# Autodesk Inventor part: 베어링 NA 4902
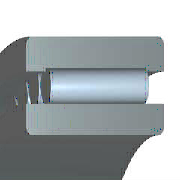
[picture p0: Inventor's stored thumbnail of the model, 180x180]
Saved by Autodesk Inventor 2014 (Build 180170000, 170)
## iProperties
IsCustomPart: 0
Manager: KYOUNG IL JANG
Company: 한국ATC센터
Created: 2009-02
Part Number: 베어링 NA 4902
Material: Steel, Mild
Description: 니들 롤러 베어링 - 경계 치수 및 공차
Document SubType Name: Modeling
Standard: KS B 2029
Standards Organization: KS
Language: ko-KR
Size Designation: NA 4902 - 15 x 28 x 13
Categories: <MemberInstance><Categories><Category DisplayName="샤프트 부품" InternalName="7f7aeb1f-a693-4053-b835-cee3144e0d98" Mnemonic="SHFT"><Category DisplayName="베어링" Inter
Density: 1 g/cm^3
Checked By: KYOUNG IL JANG
Vendor: CBT Solutions
Designer: KYOUNG IL JANG
Appearance: _시험-파란색 크롬
Author: KYOUNG IL JANG
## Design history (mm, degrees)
revolve "본체" stored, may be unused: angle "d17" = 90 deg
revolve "롤러" stored, may be unused: angle "d18" = 90 deg
body "Solid1"
sketch "스케치"
  geometry: L1 (1.857, 11.5)-(11.143, 11.5); L2 (11.143, 11.5)-(11.143, 10); L3 (13, 10)-(0, 10); L4 (1.857, 10)-(1.857, 11.5); L5 (1.857, 10.75)-(11.143, 10.75); L6 (6.5, 10.75)-(6.5, 10); L7 (0, 7.5)-(13, 7.5); L8 (0, 14)-(13, 14); L9 (13, 7.5)-(13, 10); L10 (13, 11.35)-(13, 14); L11 (1.857, 11.35)-(0, 11.35); L12 (11.143, 11.35)-(13, 11.35); L13 (-6, 0)-(36, 0) reference; L14 (0, -1.9)-(0, 14.9) reference
  constraints: 24 end point, 8 point on line, 3 midpoint, 3 parallel, 3 perpendicular, 2 symmetric about line, 1 horizontal, 1 other
  dimensions: "d6" = 15 diameter of L7 L13 (= WD); "d7" = 20 diameter of L3 L13 (= KID1); "d8" = 28 diameter of L8 L13 (= BD); "d9" = 21.5 diameter of L6.start L13 (= 0.5 x WD + 0.5 x BD); "d10" = 22.7 diameter of L12 L13 (= 0.9 x BD + 0.9 x WD - 0.8 x KID1); "d11" = 23 diameter of L1 L13 (= BD + WD - KID1); "d12" = 1.85714 distance between parallel lines of L14 L4 (= 0.142857 x KB); "d13" = 13 distance between parallel lines of L14 L9 (= KB); "d14" = 11.14286 distance between parallel lines of L14 L2 (= 0.857143 x KB)
fillet "모깎기1" dims "d0" = 0.3 (= KRS)
pattern_circular "IDS_ARRAYROLLER[SIMPL:T]" dims angle "d2" = 360 deg
other parameters: "WD" = 15 [user parameter; used in 6 equation terms], "BD" = 28 [user parameter; used in 6 equation terms], "KB" = 13 [user parameter; used in 3 equation terms], "KID1" = 20 [user parameter; used in 4 equation terms], "KRS" = 0.3 [user parameter; used in 1 equation term], "d3" = 0, "d4" = 0, "d5" = 0, "d15" = 0, "d16" = 0, "BC0" = 1.37e+07 [user parameter], "WR" = 7.5 (= 0.5 x WD) [user parameter], "BBA" = 0 [user parameter], "BC" = 1.02e+07 [user parameter], "BR" = 14 (= 0.5 x BD) [user parameter]
